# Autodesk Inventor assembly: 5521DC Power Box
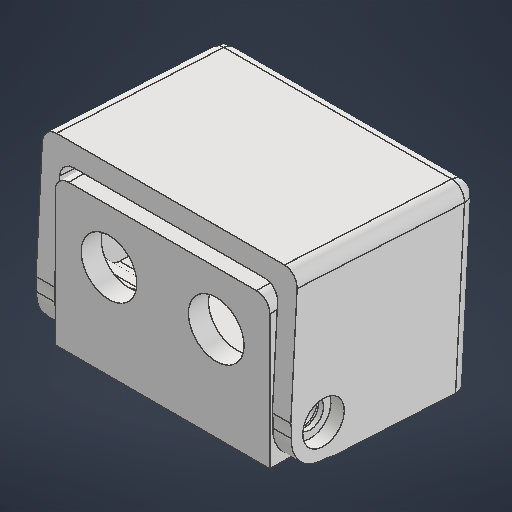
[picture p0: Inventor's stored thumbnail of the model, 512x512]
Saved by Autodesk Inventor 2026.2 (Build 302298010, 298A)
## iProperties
Created: 2026-05
Part Number: 5521DC Power Box
Document SubType Name: Assembly
Designer: work
Author: work
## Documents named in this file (3)
- C:\Users\work\Desktop\ARD_v1\ARD_hardware\PneumaticGripper_v1\5521DC Power Box.iam
- C:\Users\work\Desktop\ARD_v1\ARD_hardware\PneumaticGripper_v1\5521DC Power Box_b.ipt
- C:\Users\work\Desktop\ARD_v1\ARD_hardware\PneumaticGripper_v1\5521DC Power Box_A.ipt
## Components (2 placed, 2 different names)
1. 5521DC Power Box_b:1 — 플러쉬:1, 각도:1
2. 5521DC Power Box_A:1 — 플러쉬:1, 각도:1
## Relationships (2: Flush 1, Angle 1)
- 플러쉬:1 [Flush]: 5521DC Power Box_b:1 ↔ 5521DC Power Box_A:1
- 각도:1 [Angle]: 5521DC Power Box_b:1 ↔ 5521DC Power Box_A:1
